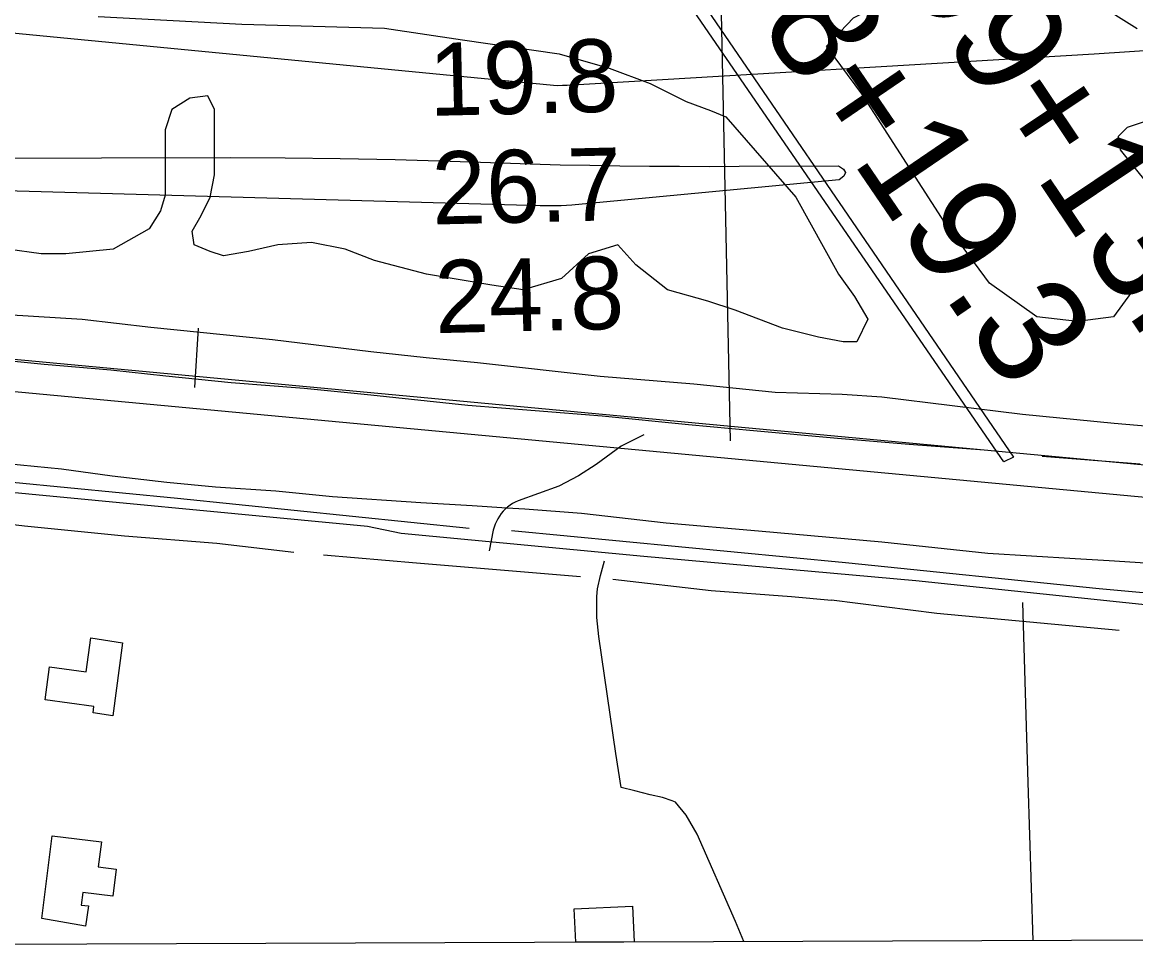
# Model space of a CAD drawing. Extents: x 3392644 to 3430565, y 576657 to 602123.
# Drawn here: x 3397410 to 3398435, y 582044 to 582895 of the extents above; entities that cross this region are included whole.
import ezdxf

# ---------------------------------------------------------------- set-up
doc = ezdxf.new("R2010")
doc.units = 0
for name, color, linetype in [('V-BLDG-OTLN', 7, 'Continuous'), ('V-CHAN-DOCK', 7, 'Continuous'), ('V-FLOD-BASE', 7, 'Continuous'), ('V-GRID-FRAM', 7, 'Continuous'), ('V-LEVE-TOET', 7, 'Continuous'), ('V-RIVR-RANG', 7, 'Continuous'), ('V-ROAD-CNTR', 7, 'Continuous'), ('V-SITE-VEGE', 7, 'Continuous'), ('V-SURV-IDEN', 7, 'Continuous'), ('V-SURV-LINE', 7, 'Continuous'), ('V-TOPO-MAJR', 7, 'Continuous'), ('V-TOPO-MINR', 7, 'Continuous'), ('V-TOPO-SHOR', 7, 'Continuous'), ('V-UTIL-LINE', 7, 'Continuous')]:
    doc.layers.add(name, color=color, linetype=linetype)

msp = doc.modelspace()

# ---------------------------------------------------------------- linework, layer by layer
at = {"layer": 'V-BLDG-OTLN'}
for p, q in [((3397917.7, 582079.3), (3397971.5, 582081.6)), ((3397919.3, 582048.5), (3397917.7, 582079.3)), ((3397971.5, 582081.6), (3397972.9, 582048.7)), ((3397972.9, 582048.7), (3397919.3, 582048.5))]:
    msp.add_line(p, q, dxfattribs=at)
for points in [[(3397502, 582324.1), (3397492.9, 582257), (3397474.8, 582259.5), (3397475.6, 582265.4), (3397430.6, 582271.5), (3397434.7, 582301.9), (3397468.4, 582297.3), (3397472.7, 582328.6)], [(3397427.7, 582070.3), (3397437.1, 582146.4), (3397482.4, 582140.8), (3397479.5, 582117.8), (3397496.1, 582115.7), (3397493, 582090.8), (3397465.3, 582094.3), (3397463.8, 582082.7), (3397470.5, 582081.9), (3397467.8, 582063.3)]]:
    msp.add_lwpolyline(points, close=True, dxfattribs=at)
at = {"layer": 'V-CHAN-DOCK'}
msp.add_lwpolyline([(3398313.2, 582490.6), (3397930.4, 583047.8), (3397907, 583046.3), (3397902.7, 583095.8), (3397942.3, 583098.8), (3397943.5, 583098.9), (3397948.7, 583099.2), (3397953.8, 583050.9), (3397943.2, 583049), (3398322.2, 582494.9), (3398313.2, 582490.6)], dxfattribs=at)
at = {"layer": 'V-FLOD-BASE'}
for points in [[(3396776.4, 582699.3), (3396872.7, 582684.8), (3396936.2, 582675.6), (3396963.1, 582671.1), (3396998.9, 582663.1), (3397057.7, 582648.9), (3397102.6, 582637.1), (3397166.4, 582620.5), (3397206.9, 582610.7), (3397227.9, 582605.4), (3397258.9, 582599.2), (3397292.9, 582593.8), (3397352.3, 582588.2), (3397429.7, 582580.5), (3397491.2, 582575.4), (3397541.7, 582569.8), (3397602, 582563.8)], [(3397602, 582563.8), (3397669.1, 582558.5), (3397730.6, 582552.3), (3397819.8, 582543), (3397881.9, 582538), (3397943.6, 582532.9), (3398023.1, 582525.2), (3398082.8, 582519.6), (3398160, 582512.4), (3398226.2, 582507.1), (3398295.3, 582501.7)], [(3398348.5, 582495.8), (3398438.9, 582488.7)]]:
    msp.add_lwpolyline(points, dxfattribs=at)
at = {"layer": 'V-GRID-FRAM'}
msp.add_lwpolyline([(3396720.3, 600227.7), (3428325.7, 600342.6), (3428399.7, 582159.3), (3396778.5, 582044.3), (3396720.3, 600227.7)], dxfattribs=at)
at = {"layer": 'V-LEVE-TOET'}
for points in [[(3398330.5, 582534.2), (3398201, 582550.3), (3398164.4, 582552.6), (3398102.9, 582554.4), (3398027.8, 582562.2), (3397941.5, 582569.3), (3397828.7, 582581.8), (3397781.4, 582586.5), (3397730.5, 582591.9), (3397640.1, 582603.1), (3397527.8, 582614.4), (3397464.6, 582621.6), (3397349.9, 582628.7), (3397305.6, 582632.9), (3397259.5, 582641.2), (3397206.3, 582651.2), (3397112.9, 582673.2), (3397065, 582686.2), (3397005.3, 582699.8), (3396935, 582713.4), (3396841, 582727.7), (3396779, 582737.7), (3396776.2, 582738.1)], [(3396776.7, 582604.8), (3396819.1, 582594.6), (3396880.6, 582582.7), (3396920.2, 582576.2), (3396968.7, 582567.3), (3397028.4, 582554.9), (3397089.8, 582541.3), (3397159, 582524.7), (3397205.7, 582515.2), (3397250, 582508.1), (3397297.3, 582502.1), (3397350.5, 582494.4), (3397395.4, 582489.1), (3397445.6, 582484.3), (3397492.3, 582477.8), (3397542.6, 582471.9), (3397587.5, 582467.7), (3397643, 582464.1), (3397695.1, 582458.8), (3397776.6, 582453.4), (3397823.9, 582450.5)], [(3398490, 582519.4), (3398415, 582525.9), (3398330.5, 582534.2)], [(3397823.9, 582450.5), (3397855.8, 582448.5), (3397872.4, 582447.5), (3397924.4, 582443.3), (3398002.4, 582434.4), (3398087.5, 582427.3), (3398201, 582417.2), (3398298.5, 582406.5), (3398378.9, 582401.7), (3398410.2, 582399.9), (3398472.3, 582395.8)]]:
    msp.add_lwpolyline(points, dxfattribs=at)
at = {"layer": 'V-RIVR-RANG'}
msp.add_line((3398061.7, 582510.1), (3398036.1, 583709.9), dxfattribs=at)
at = {"layer": 'V-ROAD-CNTR'}
msp.add_line((3397843.2, 582427.9), (3397839.5, 582408.8), dxfattribs=at)
for points in [[(3397981.7, 582515.7), (3397961.1, 582505.1), (3397938, 582488.3), (3397921.8, 582477.7), (3397903.7, 582468.4)], [(3397903.7, 582468.4), (3397866, 582454.9), (3397863.5, 582453.7), (3397861, 582452.3), (3397858.7, 582450.8), (3397856.4, 582449), (3397855.8, 582448.5), (3397854.3, 582447.2), (3397852.4, 582445.2), (3397850.5, 582443), (3397848.9, 582440.7), (3397847.4, 582438.3), (3397846.1, 582435.8), (3397845, 582433.3), (3397844, 582430.6), (3397843.2, 582427.9)], [(3397727.5, 582431.2), (3397354.4, 582466.8)], [(3398469.5, 582356.3), (3398381.7, 582365.6), (3398232.3, 582381.2), (3397981.8, 582403.5), (3397758.4, 582424.8), (3397727.5, 582431.2)], [(3398074, 582049), (3398066.3, 582067.5), (3398030.8, 582148), (3398020.8, 582165.4), (3398010.9, 582177.3), (3398007.8, 582178.5), (3397999, 582181.6), (3397987.8, 582184.1), (3397973.5, 582187.9), (3397961, 582191), (3397956, 582222.2), (3397940.5, 582330), (3397938.7, 582347.5), (3397938.7, 582366.8), (3397939.3, 582373.7), (3397941.8, 582386.1), (3397945.6, 582399.5)], [(3398340.2, 582050), (3398335.8, 582195.5), (3398330.9, 582361.3)]]:
    msp.add_lwpolyline(points, dxfattribs=at)
at = {"layer": 'V-SITE-VEGE'}
for p, q in [((3397479.4, 582900.7), (3397611.8, 582893.6)), ((3397611.8, 582893.6), (3397743, 582889.9)), ((3397743, 582889.9), (3397815, 582879.3)), ((3397815, 582879.3), (3397903.8, 582866.2)), ((3397903.8, 582866.2), (3397949.9, 582853.2)), ((3397949.9, 582853.2), (3397987.7, 582839)), ((3397987.7, 582839), (3398020.8, 582822.4)), ((3397580.5, 582827.6), (3397563.9, 582825.5)), ((3397586.7, 582815.1), (3397580.5, 582827.6)), ((3397563.9, 582825.5), (3397547.3, 582815.1)), ((3398020.8, 582822.4), (3398043.3, 582814.1)), ((3397547.3, 582815.1), (3397541.1, 582796.4)), ((3397586.7, 582754.9), (3397586.7, 582815.1)), ((3398043.3, 582814.1), (3398057.3, 582808.3)), ((3398057.3, 582808.3), (3398121.8, 582734.2)), ((3397541.1, 582796.4), (3397541.1, 582736.3)), ((3397582.5, 582734.2), (3397586.7, 582754.9)), ((3397541.1, 582736.3), (3397536.9, 582721.7)), ((3397574.2, 582717.6), (3397582.5, 582734.2)), ((3398121.8, 582734.2), (3398161.2, 582663.6)), ((3397536.9, 582721.7), (3397526.5, 582705.1)), ((3397566, 582703), (3397574.2, 582717.6)), ((3397526.5, 582705.1), (3397493.4, 582686.4)), ((3397568, 582690.6), (3397566, 582703)), ((3397675.9, 582692.7), (3397644.8, 582690.6)), ((3397707, 582686.4), (3397675.9, 582692.7)), ((3397427, 582682.3), (3397395.9, 582686.4)), ((3397449.8, 582682.3), (3397427, 582682.3)), ((3397493.4, 582686.4), (3397449.8, 582682.3)), ((3397582.5, 582684.4), (3397568, 582690.6)), ((3397595, 582680.2), (3397582.5, 582684.4)), ((3397617.8, 582684.4), (3397595, 582680.2)), ((3397644.8, 582690.6), (3397617.8, 582684.4)), ((3397734, 582676.1), (3397707, 582686.4)), ((3397931, 582682.3), (3397906.1, 582659.5)), ((3397957.9, 582690.6), (3397931, 582682.3)), ((3397974.5, 582671.9), (3397957.9, 582690.6)), ((3397781.7, 582663.6), (3397734, 582676.1)), ((3398003.6, 582649.1), (3397974.5, 582671.9)), ((3397841.8, 582653.2), (3397781.7, 582663.6)), ((3398161.2, 582663.6), (3398175.7, 582642.8)), ((3397870.8, 582649.1), (3397841.8, 582653.2)), ((3397906.1, 582659.5), (3397870.8, 582649.1)), ((3398040.9, 582638.7), (3398003.6, 582649.1)), ((3398175.7, 582642.8), (3398188.2, 582622.1)), ((3398065.8, 582630.4), (3398040.9, 582638.7)), ((3398109.4, 582613.8), (3398065.8, 582630.4)), ((3398188.2, 582622.1), (3398177.8, 582601.3)), ((3398142.5, 582605.5), (3398109.4, 582613.8)), ((3398165.4, 582601.3), (3398142.5, 582605.5)), ((3398177.8, 582601.3), (3398165.4, 582601.3))]:
    msp.add_line(p, q, dxfattribs=at)
for points in [[(3398455.7, 582659.5), (3398430.8, 582647), (3398414.2, 582624.2), (3398381.1, 582620), (3398343.7, 582624.2), (3398300.2, 582655.3), (3398258.7, 582711.3), (3398182.5, 582829.5), (3398150, 582873.4), (3398174.9, 582899.5), (3398220.2, 582922.2), (3398295, 582931.2), (3398386, 582916.4), (3398416.5, 582902), (3398436, 582889.5)], [(3398451.6, 582806.8), (3398426.7, 582798.5), (3398418.4, 582790.2), (3398420.5, 582777.8), (3398445.4, 582746.6)]]:
    msp.add_lwpolyline(points, dxfattribs=at)
at = {"layer": 'V-SURV-LINE'}
for points in [[(3397322.9, 582592.6), (3398459.3, 582486.3)], [(3398456.5, 582456.5), (3397320.1, 582562.7)]]:
    msp.add_lwpolyline(points, dxfattribs=at)
at = {"layer": 'V-TOPO-MAJR'}
msp.add_lwpolyline([(3397008.7, 582769.2), (3397600.9, 582770.7), (3397651.5, 582770.5), (3397702.2, 582770), (3397752.8, 582768.9), (3397803.5, 582767.5), (3397849.8, 582765.8), (3397877.3, 582765), (3397904.8, 582764.2), (3397932.2, 582763.7), (3397959.7, 582763.2), (3397987.2, 582762.9), (3398014.6, 582762.8), (3398042.1, 582762.7), (3398069.6, 582762.8), (3398161, 582763.3), (3398165.6, 582760.2), (3398167.6, 582757), (3398165.9, 582753.7), (3398161.7, 582750.2), (3397925.1, 582727.8), (3397915.4, 582727), (3397905.7, 582726.5), (3397896, 582726.4), (3397886.3, 582726.5), (3397076.5, 582749.1)], dxfattribs=at)
at = {"layer": 'V-TOPO-MINR'}
msp.add_lwpolyline([(3396775.5, 582965.7), (3396976.9, 582930.1), (3396993.8, 582927.3), (3397010.7, 582924.7), (3397027.7, 582922.4), (3397044.7, 582920.4), (3397898.6, 582837.3), (3397902.8, 582837.2), (3397907, 582837.3), (3397911.2, 582837.5), (3398396.3, 582866.3), (3398466, 582871)], dxfattribs=at)
at = {"layer": 'V-TOPO-SHOR'}
for points in [[(3396775.4, 582597.8), (3397099.4, 582519.1), (3397240.9, 582490.9), (3397349.6, 582477), (3397552.5, 582457.2), (3397821, 582429.5)], [(3397068.2, 582489.8), (3397145.8, 582472.6), (3397232.1, 582454.5), (3397261.1, 582449.8), (3397295.4, 582446.1), (3397345.3, 582439.8), (3397411.6, 582431.7), (3397503.6, 582422.6), (3397588.7, 582415.7), (3397659.7, 582407.5)], [(3397859.9, 582427.6), (3398167.4, 582398), (3398401, 582374.2), (3398485.1, 582366.3), (3398558.8, 582368.7), (3398605.9, 582375), (3398667.3, 582397.7), (3398736.8, 582434.9), (3398781.8, 582457.6), (3398806.4, 582465.9), (3398833, 582478.2), (3398888.2, 582492.8), (3398894.4, 582492.8), (3398968.2, 582493.1)], [(3397686.9, 582405), (3397772.6, 582397.8), (3397846.1, 582391.6), (3397923.4, 582385)], [(3397953.3, 582382.8), (3398043.7, 582372.4), (3398117.9, 582366.8), (3398154.7, 582363.3)], [(3398419.6, 582335.4), (3398251.5, 582351.2), (3398154.7, 582363.3)]]:
    msp.add_lwpolyline(points, dxfattribs=at)
at = {"layer": 'V-UTIL-LINE'}
msp.add_line((3397568.5, 582559.1), (3397571.7, 582613.6), dxfattribs=at)

# ---------------------------------------------------------------- texts
at = {"layer": 'V-RIVR-RANG'}
for s, p in [('19.8', (3397784.7, 582809.1)), ('26.7', (3397787.4, 582709.1)), ('24.8', (3397790, 582609.1))]:
    msp.add_text(s, height=67, rotation=1.3583, dxfattribs=at).set_placement(p)
at = {"layer": 'V-SURV-IDEN'}
for s, rotation, p in [('98+19.3', 304.3014, (3398044.9, 582955.4)), ('99+13.4', 303.814, (3398215.4, 582942.1))]:
    msp.add_text(s, height=100, rotation=rotation, dxfattribs=at).set_placement(p)

doc.saveas('drawing.dxf')
